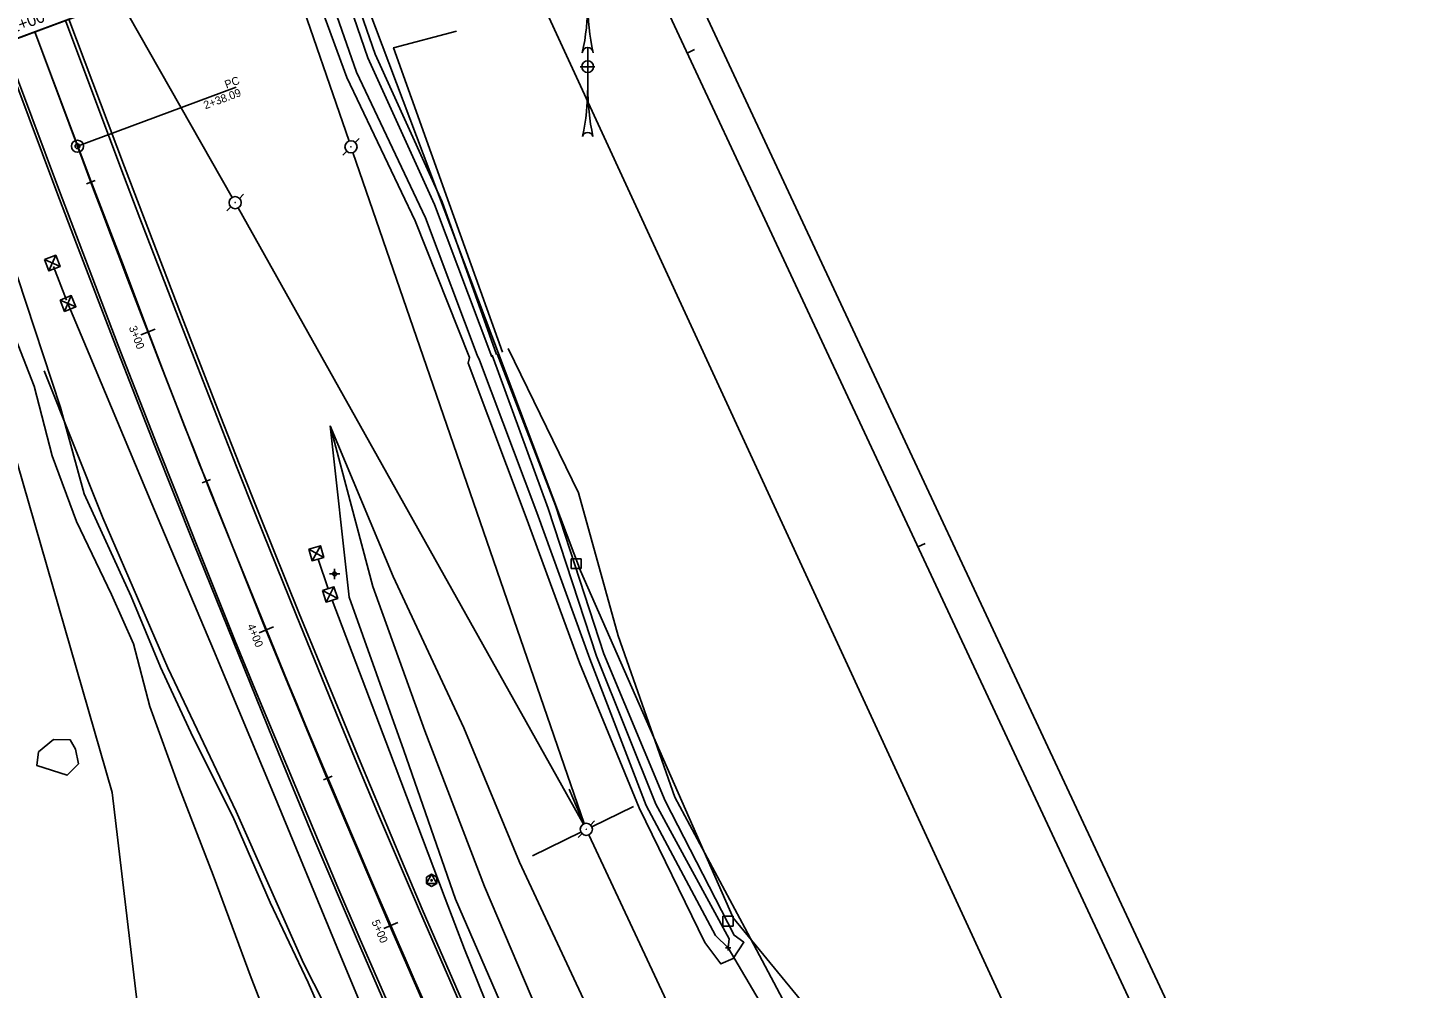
# Model space of a CAD drawing. Extents: x 1040364 to 1041050, y 1127298 to 1128100.
# Drawn here: x 1040619.4 to 1041050.3, y 1127649.8 to 1127949.4 of the extents above; entities that cross this region are included whole.
import ezdxf

# ---------------------------------------------------------------- set-up
doc = ezdxf.new("R2010")
doc.units = 0
for name, color, linetype in [('AC_P', 7, 'Continuous'), ('ACP_P', 7, 'Continuous'), ('ACSC_P_T', 7, 'Continuous'), ('ACSCT_P', 7, 'Continuous'), ('ACSR_P_T', 7, 'Continuous'), ('ACSRT_P', 7, 'Continuous'), ('CBS', 7, 'Continuous'), ('clip boundary', 7, 'Continuous'), ('DCP', 7, 'Continuous'), ('DELB', 7, 'Continuous'), ('DINV', 7, 'Continuous'), ('LAWA', 7, 'Continuous'), ('LAWE', 7, 'Continuous'), ('LELB', 7, 'Continuous'), ('MHB', 7, 'Continuous'), ('MPM', 7, 'Continuous'), ('NML_P', 7, 'Continuous'), ('NML_P_T', 7, 'Continuous'), ('NNA_P', 7, 'Continuous'), ('PE', 7, 'Continuous'), ('RGA', 7, 'Continuous'), ('RGC', 7, 'Continuous'), ('S', 7, 'Continuous'), ('SHEET_BORDER', 7, 'Continuous'), ('SHEET_BORDER_CUT', 7, 'Continuous'), ('STFBY', 7, 'Continuous'), ('STPBY', 7, 'Continuous'), ('STSEW', 7, 'Continuous'), ('UEO', 7, 'Continuous'), ('UP', 7, 'Continuous'), ('UPGW', 7, 'Continuous')]:
    doc.layers.add(name, color=color, linetype=linetype)

msp = doc.modelspace()

# ---------------------------------------------------------------- linework, layer by layer
at = {"layer": 'AC_P'}
msp.add_line((1040621.67, 1127948.13), (1040634.94, 1127912.44), dxfattribs=at)
msp.add_arc((1045321.32, 1129655.39), 5000, 200.40109, 205.67201, dxfattribs=at)
at = {"layer": 'ACP_P'}
for radius in [1.88, 0.747, 0.156]:
    msp.add_circle((1040634.94, 1127912.44), radius, dxfattribs=at)
at = {"layer": 'ACSCT_P'}
msp.add_lwpolyline([(1040634.94, 1127912.44), (1040684.43, 1127930.84)], dxfattribs=at)
at = {"layer": 'ACSRT_P'}
for points in [[(1040623.92, 1127948.97), (1040619.42, 1127947.3)], [(1040640.46, 1127901.78), (1040637.76, 1127900.77)], [(1040659.12, 1127855.41), (1040654.65, 1127853.68)], [(1040676.46, 1127808.52), (1040673.79, 1127807.46)], [(1040696.05, 1127762.53), (1040691.61, 1127760.71)], [(1040714.33, 1127716), (1040711.67, 1127714.88)], [(1040734.83, 1127670.41), (1040730.43, 1127668.5)]]:
    msp.add_lwpolyline(points, dxfattribs=at)
at = {"layer": 'CBS'}
for points in [[(1040745.38, 1127681.64), (1040747.01, 1127682.59), (1040747.01, 1127684.48), (1040745.38, 1127685.42), (1040743.74, 1127684.48), (1040743.74, 1127682.59)], [(1040747.01, 1127682.59), (1040745.38, 1127685.42), (1040743.74, 1127682.59)]]:
    msp.add_lwpolyline(points, close=True, dxfattribs=at)
msp.add_circle((1040745.38, 1127683.53), 0.226, dxfattribs=at)
at = {"layer": 'clip boundary'}
for points in [[(1040762.51, 1128099.9), (1041050.31, 1127483.8), (1040651.66, 1127297.58), (1040363.86, 1127913.67)], [(1040504.79, 1127904.67), (1040760.34, 1127999.71), (1040984.84, 1127512.73), (1040710.81, 1127382.18)]]:
    msp.add_lwpolyline(points, close=True, dxfattribs=at)
at = {"layer": 'DCP'}
msp.add_line((1040837.86, 1127662.43), (1040848.54, 1127644.26), dxfattribs=at)
at = {"layer": 'DELB'}
for points in [[(1040711.25, 1127981.45), (1040725.46, 1127940.06), (1040746.27, 1127894.3), (1040764.19, 1127846.72)], [(1040713.54, 1127982.3), (1040727.79, 1127941.15), (1040748.7, 1127895.13), (1040765.65, 1127847.45)], [(1040757.16, 1127846.54), (1040740.28, 1127889.15), (1040718.94, 1127933.92), (1040702.72, 1127978.14), (1040702.66, 1127978.26)], [(1040759.55, 1127847.27), (1040743.47, 1127890.1), (1040721.93, 1127935.56), (1040706.63, 1127979.42), (1040706.5, 1127979.69)], [(1040756.77, 1127844.76), (1040774.84, 1127796.72), (1040791.49, 1127751.33), (1040810.16, 1127706.14), (1040830.58, 1127664.12), (1040835.53, 1127657.49), (1040839.44, 1127659.18), (1040842.77, 1127664.21), (1040839.78, 1127666.39), (1040818.26, 1127708.28), (1040799.05, 1127754.12), (1040783.98, 1127800.39), (1040765.82, 1127847.66)], [(1040760.28, 1127845.72), (1040759.55, 1127847.27)], [(1040760.28, 1127845.72), (1040778.22, 1127798.22), (1040794.7, 1127752.56), (1040812.34, 1127706.88), (1040833.87, 1127666.29), (1040837.86, 1127662.43), (1040838.2, 1127665.3), (1040815.26, 1127707.23), (1040796.85, 1127753.39), (1040781.74, 1127799.46), (1040764.28, 1127847.32)], [(1040764.28, 1127847.32), (1040764.19, 1127846.72)], [(1040765.82, 1127847.66), (1040765.65, 1127847.45)], [(1040756.77, 1127844.76), (1040757.16, 1127846.54)]]:
    msp.add_lwpolyline(points, dxfattribs=at)
at = {"layer": 'DINV'}
for q in [(1040837.07, 1127662.43), (1040837.86, 1127663.22), (1040838.65, 1127662.43), (1040837.86, 1127661.64)]:
    msp.add_line((1040837.86, 1127662.43), q, dxfattribs=at)
at = {"layer": 'LAWA'}
for points in [[(1040767.5, 1127848.26), (1040750.82, 1127894.62), (1040733.51, 1127943.15), (1040753.19, 1127948.3)], [(1040583.91, 1127860.63), (1040612.35, 1127873.83), (1040616.26, 1127871.74), (1040629.69, 1127830.98), (1040637.02, 1127804.07), (1040651.71, 1127772.02), (1040660.81, 1127750.01), (1040670.93, 1127728.26), (1040683.43, 1127703.39), (1040695, 1127676.62), (1040706.92, 1127651.68), (1040723.86, 1127612.81), (1040738.89, 1127579.03), (1040755.95, 1127542.69), (1040767.31, 1127518.61), (1040755.88, 1127521.48)], [(1040974.44, 1127535.31), (1040970.5, 1127539.17), (1040948.07, 1127547.34), (1040930.81, 1127543.39), (1040892.81, 1127585.99), (1040867.58, 1127622.42), (1040843.05, 1127668.73), (1040821.26, 1127709.49), (1040803.57, 1127759.72), (1040791.15, 1127804.33), (1040769.23, 1127849.37)]]:
    msp.add_lwpolyline(points, dxfattribs=at)
at = {"layer": 'LAWE'}
msp.add_lwpolyline([(1040622.83, 1127723.63), (1040627.49, 1127727.41), (1040632.67, 1127727.29), (1040634.36, 1127724.38), (1040635.23, 1127719.84), (1040631.68, 1127716.29), (1040622.28, 1127719.29), (1040622.83, 1127723.63)], dxfattribs=at)
at = {"layer": 'LELB'}
for points in [[(1040810.73, 1127429.78), (1040803.7, 1127447.62), (1040790.28, 1127475.04), (1040767.31, 1127518.61), (1040755.95, 1127542.69), (1040738.89, 1127579.03), (1040723.86, 1127612.81), (1040706.92, 1127651.68), (1040695, 1127676.62), (1040683.43, 1127703.39), (1040670.93, 1127728.26), (1040660.81, 1127750.01), (1040651.71, 1127772.02), (1040637.02, 1127804.07), (1040629.69, 1127830.98), (1040616.26, 1127871.74), (1040612.35, 1127873.83), (1040609.66, 1127871.77), (1040608.53, 1127867.34), (1040606.04, 1127852.48)], [(1040614.83, 1127854.62), (1040621.41, 1127837.65), (1040627.08, 1127815.86), (1040634.65, 1127795.46), (1040645.6, 1127772.71), (1040652.36, 1127757.32), (1040657.51, 1127737.76), (1040666.51, 1127712.78), (1040677.3, 1127685.09), (1040689.11, 1127653.1), (1040703.01, 1127617.33), (1040698.4, 1127596.43), (1040696.45, 1127571.66), (1040693.76, 1127556.81), (1040687.36, 1127532.93), (1040690.81, 1127510.27), (1040692.18, 1127477.93)], [(1040749.93, 1127567.85), (1040727.85, 1127613.5), (1040705.48, 1127657.66), (1040684.38, 1127704.97), (1040663.13, 1127749.8), (1040642.83, 1127796.58), (1040624.51, 1127842.39)], [(1040713.7, 1127825.26), (1040727.06, 1127775.17), (1040743.3, 1127730.12), (1040761.87, 1127681.6), (1040780.54, 1127637.65), (1040801.46, 1127591.59), (1040822.93, 1127546.17), (1040844.27, 1127501.4), (1040862.43, 1127454.57), (1040862.49, 1127454.44)], [(1040713.7, 1127825.26), (1040719.71, 1127771.8)], [(1040713.7, 1127825.26), (1040733.39, 1127778.3)], [(1040733.39, 1127778.3), (1040755.39, 1127731.1), (1040772.83, 1127689.2), (1040794.16, 1127643.36), (1040815.07, 1127595.54), (1040835.22, 1127552.16), (1040853.9, 1127512.99)], [(1040857.81, 1127452.21), (1040835.32, 1127496.78), (1040813.91, 1127542.4), (1040792.2, 1127586.64), (1040772.38, 1127632.65), (1040752.78, 1127677.66), (1040736.76, 1127724.02), (1040719.71, 1127771.8)]]:
    msp.add_lwpolyline(points, dxfattribs=at)
at = {"layer": 'MHB'}
for points in [[(1040715.1, 1127982.88), (1040725.76, 1127955.01), (1040791.8, 1127780.06), (1040839.44, 1127671.87), (1040933.95, 1127556.77), (1040967.39, 1127504.42)], [(1040689.65, 1127435.84), (1040667.39, 1127529.05), (1040645.74, 1127710.89), (1040582.66, 1127929.61), (1040581.63, 1127933.24)]]:
    msp.add_lwpolyline(points, dxfattribs=at)
at = {"layer": 'MPM'}
for p, q in [((1040788.89, 1127780.74), (1040788.89, 1127783.81)), ((1040788.89, 1127783.81), (1040792.04, 1127783.81)), ((1040792.04, 1127783.81), (1040792.04, 1127780.74)), ((1040792.04, 1127780.74), (1040788.89, 1127780.74)), ((1040836.23, 1127669.25), (1040836.23, 1127672.31)), ((1040836.23, 1127672.31), (1040839.38, 1127672.31)), ((1040839.38, 1127672.31), (1040839.38, 1127669.25)), ((1040839.38, 1127669.25), (1040836.23, 1127669.25))]:
    msp.add_line(p, q, dxfattribs=at)
at = {"layer": 'NML_P'}
msp.add_line((1040504.79, 1127904.67), (1040760.34, 1127999.71), dxfattribs=at)
at = {"layer": 'NNA_P'}
for p, q in [((1040794.07, 1127930.87), (1040794.07, 1127943.25)), ((1040791.74, 1127937.23), (1040796.29, 1127937.23))]:
    msp.add_line(p, q, dxfattribs=at)
msp.add_circle((1040794.05, 1127937.25), 1.81, dxfattribs=at)
for centre, radius, start, end in [((1040720.98, 1127957.19), 73.09, 347.6515, 0.1139), ((1040867.16, 1127957.19), 73.09, 179.8844, 192.3468), ((1040794.07, 1127941.56), 1.69, 359.9991, 179.9991), ((1040720.98, 1127930.86), 73.09, 347.8917, 0.0159), ((1040867.16, 1127930.85), 73.09, 179.9824, 192.1066), ((1040794.07, 1127915.06), 1.69, 15.894, 164.1052)]:
    msp.add_arc(centre, radius, start, end, dxfattribs=at)
at = {"layer": 'PE'}
for points in [[(1040632.25, 1127952.07), (1040649.62, 1127906.04), (1040655.5, 1127890.52), (1040667.36, 1127859.52), (1040679.42, 1127828.44), (1040685.53, 1127812.93), (1040691.68, 1127797.52), (1040704.12, 1127766.75), (1040723.07, 1127720.54), (1040735.94, 1127689.83), (1040742.48, 1127674.51), (1040755.79, 1127643.96), (1040762.56, 1127628.73), (1040769.44, 1127613.48), (1040783.38, 1127583.06), (1040797.39, 1127552.96), (1040804.47, 1127537.94), (1040826.05, 1127492.6), (1040847.29, 1127447.58), (1040847.43, 1127447.27)], [(1040827.22, 1127437.64), (1040826.9, 1127438.31), (1040805.61, 1127483.11), (1040784.16, 1127528.43), (1040762.74, 1127574.12), (1040748.8, 1127604.56), (1040741.94, 1127619.83), (1040735.2, 1127635.03), (1040721.93, 1127665.52), (1040708.68, 1127696.59), (1040702.17, 1127712.18), (1040695.93, 1127727.39), (1040683.59, 1127757.86), (1040671.21, 1127788.47), (1040665.07, 1127803.8), (1040658.98, 1127819.2), (1040646.94, 1127850.06), (1040634.62, 1127882.06), (1040628.54, 1127898.1), (1040611.22, 1127944.25)]]:
    msp.add_lwpolyline(points, dxfattribs=at)
at = {"layer": 'RGA'}
for p, q in [((1040624.62, 1127877.11), (1040629.5, 1127874.93)), ((1040628.15, 1127878.46), (1040625.98, 1127873.58)), ((1040631.56, 1127864.47), (1040627.47, 1127874.97)), ((1040629.51, 1127864.45), (1040634.44, 1127862.38)), ((1040633.01, 1127865.88), (1040630.94, 1127860.95)), ((1040707.06, 1127786.79), (1040711.75, 1127784.23)), ((1040710.69, 1127787.86), (1040708.13, 1127783.17)), ((1040713.11, 1127774.47), (1040710.01, 1127783.72)), ((1040711.33, 1127773.89), (1040716.09, 1127771.46)), ((1040714.92, 1127775.06), (1040712.49, 1127770.3))]:
    msp.add_line(p, q, dxfattribs=at)
for points in [[(1040624.62, 1127877.11), (1040628.15, 1127878.46), (1040629.5, 1127874.93), (1040625.98, 1127873.58)], [(1040629.51, 1127864.45), (1040633.01, 1127865.88), (1040634.44, 1127862.38), (1040630.94, 1127860.95)], [(1040707.06, 1127786.79), (1040710.69, 1127787.86), (1040711.75, 1127784.23), (1040708.13, 1127783.17)], [(1040711.33, 1127773.89), (1040714.92, 1127775.06), (1040716.09, 1127771.46), (1040712.49, 1127770.3)]]:
    msp.add_lwpolyline(points, close=True, dxfattribs=at)
at = {"layer": 'RGC'}
for points in [[(1040821.91, 1127435.11), (1040821.71, 1127435.54), (1040814.44, 1127450.47), (1040799.42, 1127480.1), (1040784.36, 1127510.25), (1040776.98, 1127525.39), (1040767.39, 1127545.45), (1040762.66, 1127555.51), (1040755.68, 1127570.65), (1040748.81, 1127585.88), (1040735.39, 1127616.49), (1040722.27, 1127647.33), (1040715.84, 1127662.8), (1040696.64, 1127709.35), (1040677.37, 1127755.44), (1040658.12, 1127800.96), (1040638.6, 1127847.62), (1040631.97, 1127863.41)], [(1040714.38, 1127770.91), (1040732.29, 1127723.82), (1040749.62, 1127677.89), (1040755.63, 1127662.08), (1040762.02, 1127646.41), (1040768.42, 1127631.69), (1040775.21, 1127616.41), (1040789.21, 1127586.06), (1040810.12, 1127540.99), (1040831.75, 1127495.43), (1040853.16, 1127450.13), (1040853.21, 1127450.02)]]:
    msp.add_lwpolyline(points, dxfattribs=at)
at = {"layer": 'S'}
for p, q in [((1040716.71, 1127779.07), (1040713.56, 1127779.07)), ((1040715.13, 1127780.64), (1040715.13, 1127777.49))]:
    msp.add_line(p, q, dxfattribs=at)
msp.add_circle((1040715.13, 1127779.07), 0.591, dxfattribs=at)
at = {"layer": 'SHEET_BORDER'}
for p, q in [((1040825.12, 1127941.51), (1040827.39, 1127942.57)), ((1040897.07, 1127787.48), (1040899.33, 1127788.54))]:
    msp.add_line(p, q, dxfattribs=at)
msp.add_lwpolyline([(1040652.69, 1127325.65), (1040649.37, 1127326.86), (1040384.85, 1127893.12), (1040386.05, 1127896.45), (1040761.49, 1128071.82), (1040764.81, 1128070.62), (1041029.33, 1127504.35), (1041028.12, 1127501.03)], close=True, dxfattribs=at)
at = {"layer": 'SHEET_BORDER_CUT'}
msp.add_lwpolyline([(1040363.86, 1127913.67), (1040651.66, 1127297.58), (1041050.31, 1127483.8), (1040762.51, 1128099.9)], close=True, dxfattribs=at)
at = {"layer": 'STFBY'}
msp.add_lwpolyline([(1040837.33, 1127442.46), (1040837.03, 1127443.08), (1040815.99, 1127487.47), (1040794.41, 1127532.94), (1040773.27, 1127578.07), (1040759.07, 1127608.84), (1040752.08, 1127624.28), (1040745.3, 1127639.51), (1040732.01, 1127670.09), (1040712.44, 1127716.22), (1040699.8, 1127746.64), (1040693.6, 1127761.89), (1040675.04, 1127808.28), (1040673.1, 1127813.03)], dxfattribs=at)
at = {"layer": 'STPBY'}
msp.add_lwpolyline([(1040673.1, 1127813.03), (1040662.25, 1127840.75), (1040656.96, 1127854.66), (1040649.5, 1127874.61), (1040639.08, 1127901.67), (1040621.67, 1127948.13)], dxfattribs=at)
at = {"layer": 'STSEW'}
for points in [[(1040631.23, 1127951.69), (1040648.51, 1127905.59), (1040654.39, 1127890.06), (1040666.38, 1127859.09), (1040684.56, 1127812.57), (1040690.71, 1127797.15), (1040703.13, 1127766.35), (1040715.7, 1127735.48), (1040722.06, 1127720.07), (1040728.5, 1127704.72), (1040741.59, 1127674.11), (1040754.93, 1127643.58), (1040761.69, 1127628.35), (1040768.56, 1127613.09), (1040782.51, 1127582.66), (1040803.66, 1127537.47), (1040825.13, 1127492.13), (1040846.44, 1127447.18), (1040846.59, 1127446.87)], [(1040828.27, 1127438.14), (1040827.96, 1127438.8), (1040806.65, 1127483.62), (1040785.12, 1127528.86), (1040763.78, 1127574.53), (1040749.77, 1127604.92), (1040742.86, 1127620.16), (1040736.1, 1127635.32), (1040722.83, 1127665.76), (1040716.16, 1127681.33), (1040702.99, 1127712.55), (1040690.38, 1127742.93), (1040684.16, 1127758.16), (1040671.9, 1127788.75), (1040665.82, 1127804.07), (1040659.73, 1127819.47), (1040647.66, 1127850.31), (1040635.42, 1127882.35), (1040629.38, 1127898.4), (1040612.07, 1127944.56)]]:
    msp.add_lwpolyline(points, dxfattribs=at)
at = {"layer": 'UEO'}
for points in [[(1040702.54, 1127963.79), (1040719.62, 1127914.05)], [(1040650.92, 1127953.15), (1040683.17, 1127896.49)], [(1040720.86, 1127910.47), (1040793.01, 1127701.22)], [(1040685.03, 1127893.2), (1040792.7, 1127701.09)], [(1040794.43, 1127697.72), (1040887.71, 1127498.43)]]:
    msp.add_lwpolyline(points, dxfattribs=at)
at = {"layer": 'UP'}
for p, q in [((1040720.3, 1127912.26), (1040720.18, 1127912.26)), ((1040720.24, 1127912.32), (1040720.24, 1127912.2)), ((1040721.57, 1127913.6), (1040722.82, 1127914.86)), ((1040718.91, 1127910.92), (1040717.66, 1127909.66)), ((1040684.17, 1127894.85), (1040684.04, 1127894.85)), ((1040684.1, 1127894.91), (1040684.1, 1127894.79)), ((1040685.44, 1127896.19), (1040686.69, 1127897.45)), ((1040682.77, 1127893.51), (1040681.52, 1127892.25)), ((1040794.96, 1127700.78), (1040796.21, 1127702.04)), ((1040792.3, 1127698.1), (1040791.05, 1127696.84)), ((1040793.69, 1127699.44), (1040793.57, 1127699.44)), ((1040793.63, 1127699.5), (1040793.63, 1127699.37))]:
    msp.add_line(p, q, dxfattribs=at)
for centre in [(1040720.24, 1127912.26), (1040684.1, 1127894.85), (1040793.63, 1127699.44)]:
    msp.add_circle(centre, 1.89, dxfattribs=at)
at = {"layer": 'UPGW'}
for points in [[(1040788.24, 1127711.93), (1040792.88, 1127701.17)], [(1040808.38, 1127706.54), (1040795.33, 1127700.26)], [(1040776.81, 1127691.17), (1040791.93, 1127698.6)]]:
    msp.add_lwpolyline(points, dxfattribs=at)

# ---------------------------------------------------------------- texts
at = {"layer": 'ACSC_P_T'}
for s, p in [('PC', (1040681.4, 1127930.38)), ('2+38.09', (1040674.82, 1127923.94))]:
    msp.add_text(s, height=2.496, rotation=20.4011, dxfattribs=at).set_placement(p)
at = {"layer": 'ACSR_P_T'}
for s, rotation, p in [('3+00', 291.1106, (1040650.91, 1127855.9)), ('4+00', 292.2565, (1040687.81, 1127762.89)), ('5+00', 293.4024, (1040726.59, 1127670.6))]:
    msp.add_text(s, height=2.496, rotation=rotation, dxfattribs=at).set_placement(p)
at = {"layer": 'NML_P_T'}
msp.add_text('MATCHLINE STA. 2+00 - SEE DWG. GNP-01', height=3.744, rotation=20.4011, dxfattribs=at).set_placement((1040574.42, 1127932.6))

doc.saveas('drawing.dxf')
